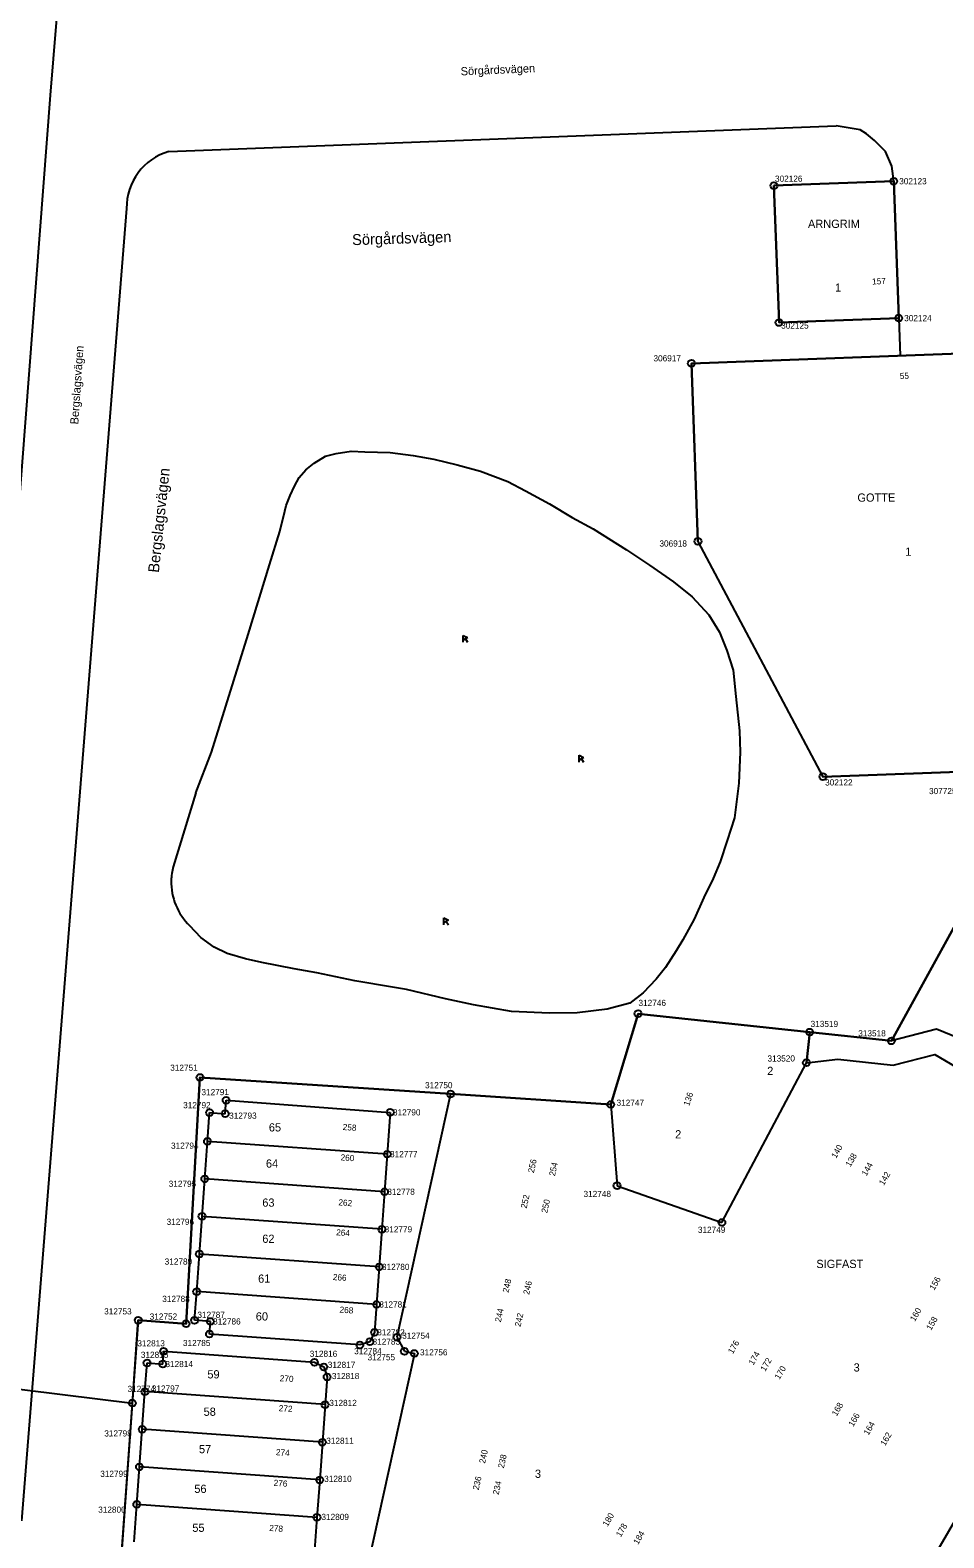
# Model space of a CAD drawing. Extents: x 141995 to 152570, y 6580184 to 6586000.
# Drawn here: x 142442.1 to 142575.6, y 6585148.7 to 6585368.8 of the extents above; entities that cross this region are included whole.
import ezdxf

# ---------------------------------------------------------------- set-up
doc = ezdxf.new("R2010")
doc.units = 0
for name, color, linetype in [('Level 10', 7, 'Continuous'), ('Level 12', 7, 'Continuous'), ('Level 13', 7, 'Continuous'), ('Level 20', 7, 'Continuous'), ('Level 21', 7, 'Continuous'), ('Level 33', 7, 'Continuous'), ('Level 40', 7, 'Continuous'), ('Level 43', 7, 'Continuous'), ('Level 5', 7, 'Continuous'), ('Level 50', 7, 'Continuous'), ('Level 51', 7, 'Continuous'), ('Level 53', 7, 'Continuous'), ('Level 54', 7, 'Continuous'), ('Level 55', 7, 'Continuous'), ('Level 58', 7, 'Continuous'), ('Level 59', 7, 'Continuous'), ('Level 6', 7, 'Continuous'), ('Level 7', 7, 'Continuous'), ('Level 8', 7, 'Continuous')]:
    doc.layers.add(name, color=color, linetype=linetype)

msp = doc.modelspace()

# ---------------------------------------------------------------- linework, layer by layer
at = {"layer": 'Level 10'}
for centre in [(142550.74, 6585346.1), (142568.23, 6585346.74), (142551.48, 6585326.11), (142568.96, 6585326.75), (142538.68, 6585320.14), (142539.64, 6585294.16), (142557.9, 6585259.8), (142530.89, 6585225.21), (142555.96, 6585222.52), (142567.89, 6585221.24), (142555.48, 6585218.05), (142466.9, 6585215.9), (142503.51, 6585213.49), (142470.72, 6585212.57), (142526.9, 6585211.96), (142468.29, 6585210.76), (142470.58, 6585210.6), (142494.69, 6585210.8), (142467.99, 6585206.57), (142494.26, 6585204.7), (142467.6, 6585201.09), (142527.82, 6585200.09), (142493.86, 6585199.21), (142467.2, 6585195.61), (142493.47, 6585193.73), (142543.13, 6585194.73), (142466.81, 6585190.12), (142493.08, 6585188.24), (142466.42, 6585184.63), (142492.69, 6585182.76), (142457.88, 6585180.44), (142466.12, 6585180.44), (142468.42, 6585180.28), (142464.86, 6585179.94), (142468.28, 6585178.44), (142492.39, 6585178.69), (142495.67, 6585177.98), (142461.59, 6585175.92), (142490.25, 6585176.84), (142491.71, 6585177.32), (142496.75, 6585175.92), (142459.16, 6585174.22), (142461.45, 6585174.06), (142483.62, 6585174.31), (142484.98, 6585173.63), (142498.21, 6585175.6), (142485.47, 6585172.18), (142458.86, 6585170.03), (142457.02, 6585168.35), (142485.17, 6585168.14), (142458.46, 6585164.54), (142484.78, 6585162.65), (142458.06, 6585159.05), (142484.38, 6585157.15), (142457.67, 6585153.57), (142483.99, 6585151.67)]:
    msp.add_circle(centre, 0.5, dxfattribs=at)
at = {"layer": 'Level 12'}
for p, q in [((142505.33, 6585279.43), (142505.33, 6585280.43)), ((142505.33, 6585280.43), (142505.98, 6585280.13)), ((142505.98, 6585280.13), (142505.33, 6585279.73)), ((142505.66, 6585279.93), (142505.98, 6585279.43)), ((142522.29, 6585261.93), (142522.29, 6585262.93)), ((142522.29, 6585262.93), (142522.94, 6585262.63)), ((142522.94, 6585262.63), (142522.29, 6585262.23)), ((142522.61, 6585262.43), (142522.94, 6585261.93)), ((142502.54, 6585238.18), (142502.54, 6585239.18)), ((142502.54, 6585239.18), (142503.19, 6585238.88)), ((142503.19, 6585238.88), (142502.54, 6585238.48)), ((142502.87, 6585238.68), (142503.19, 6585238.18))]:
    msp.add_line(p, q, dxfattribs=at)
for points in [[(142479.27, 6585298.57), (142479.48, 6585299.38), (142480.07, 6585300.85), (142480.7, 6585302.24), (142481.4, 6585303.49), (142482.36, 6585304.6), (142483.56, 6585305.57), (142485.22, 6585306.58), (142486.8, 6585307.01), (142488.99, 6585307.32), (142490.98, 6585307.25), (142494.68, 6585307.14), (142498.06, 6585306.69), (142501.04, 6585306.15), (142504.47, 6585305.31), (142507.89, 6585304.39), (142511.88, 6585302.89), (142514.45, 6585301.56), (142517.94, 6585299.65), (142521.27, 6585297.64), (142524.32, 6585295.97), (142529.18, 6585292.93), (142532.55, 6585290.7), (142536.07, 6585288.26), (142538.8, 6585286.08), (142541.23, 6585283.45), (142542.8, 6585280.92), (142543.87, 6585278.22), (142544.78, 6585275.35), (142545.19, 6585271.5), (142545.7, 6585266.48), (142545.79, 6585263.38), (142545.61, 6585258.85), (142544.96, 6585253.81), (142543.92, 6585250.49), (142542.9, 6585247.4), (142541.87, 6585244.94), (142540.51, 6585242.19), (142539.06, 6585238.99), (142537.43, 6585235.99), (142536.44, 6585234.37)], [(142466.31, 6585257.46), (142468.57, 6585263.38), (142473.92, 6585280.57), (142477.03, 6585290.72), (142478.55, 6585295.61), (142479.27, 6585298.57)], [(142466.31, 6585257.46), (142462.97, 6585246.65)], [(142473.57, 6585233.2), (142470.85, 6585233.98), (142468.95, 6585234.93), (142467.04, 6585236.31), (142465.42, 6585238.05)], [(142536.44, 6585234.37), (142534.88, 6585231.94), (142533.51, 6585230.26), (142531.64, 6585228.25), (142529.67, 6585226.72), (142526.37, 6585225.88), (142521.99, 6585225.35), (142517.95, 6585225.26), (142512.4, 6585225.55), (142506.85, 6585226.49), (142502.74, 6585227.36)], [(142502.74, 6585227.36), (142497.04, 6585228.72), (142495, 6585229.08), (142489.54, 6585230.02), (142483.95, 6585231.17), (142480.67, 6585231.75), (142475.94, 6585232.66), (142473.57, 6585233.2)]]:
    msp.add_lwpolyline(points, dxfattribs=at)
for centre, radius, start, end in [((142471.53, 6585244.43), 8.84, 165.4662, 178.5896), ((142471.52, 6585244.43), 8.83, 178.607, 226.2702)]:
    msp.add_arc(centre, radius, start, end, dxfattribs=at)
at = {"layer": 'Level 13'}
for points in [[(142462.35, 6585351.07), (142559.81, 6585354.83)], [(142568.23, 6585346.74), (142567.94, 6585348.96), (142567.05, 6585351.06), (142565.4, 6585352.67), (142564.26, 6585353.68), (142563.31, 6585354.23), (142559.81, 6585354.83)], [(142456.17, 6585342.76), (142440.83, 6585151.19)], [(142568.96, 6585326.75), (142569.16, 6585321.26)]]:
    msp.add_lwpolyline(points, dxfattribs=at)
msp.add_arc((142464.66, 6585342.9), 8.49, 105.7848, 180.9356, dxfattribs=at)
at = {"layer": 'Level 20'}
msp.add_lwpolyline([(142468.56, 6585644.66), (142445.03, 6585359.28), (142436.21, 6585244.62)], dxfattribs=at)
at = {"layer": 'Level 21'}
msp.add_lwpolyline([(142468.56, 6585644.66), (142445.03, 6585359.28), (142436.21, 6585244.62)], dxfattribs=at)
at = {"layer": 'Level 33'}
msp.add_lwpolyline([(142567.89, 6585221.24), (142555.96, 6585222.52), (142555.48, 6585218.05), (142560.06, 6585218.56), (142568.15, 6585217.7), (142574.22, 6585219.27), (142604.74, 6585201.34), (142607.64, 6585198.99), (142608.58, 6585196.76), (142613.29, 6585200.9), (142611.16, 6585202.1), (142607.15, 6585205.72), (142585.42, 6585218.45), (142574.48, 6585222.95)], close=True, dxfattribs=at)
at = {"layer": 'Level 5'}
for points in [[(142550.74, 6585346.1), (142568.23, 6585346.74)], [(142551.48, 6585326.11), (142550.74, 6585346.1)], [(142568.23, 6585346.74), (142568.96, 6585326.75)], [(142568.96, 6585326.75), (142551.48, 6585326.11)], [(142538.68, 6585320.14), (142583.16, 6585321.77)], [(142539.64, 6585294.16), (142538.68, 6585320.14)], [(142539.64, 6585294.16), (142557.9, 6585259.8)], [(142598.87, 6585261.3), (142557.9, 6585259.8)], [(142567.89, 6585221.24), (142578.61, 6585240.72)], [(142526.9, 6585211.96), (142530.89, 6585225.21)], [(142530.89, 6585225.21), (142555.96, 6585222.52)], [(142555.96, 6585222.52), (142567.89, 6585221.24)], [(142464.86, 6585179.94), (142466.9, 6585215.9)], [(142466.9, 6585215.9), (142503.51, 6585213.49)], [(142503.51, 6585213.49), (142526.9, 6585211.96)], [(142457.02, 6585168.35), (142457.88, 6585180.44)], [(142457.88, 6585180.44), (142464.86, 6585179.94)], [(142452.49, 6585105.64), (142457.02, 6585168.35)]]:
    msp.add_lwpolyline(points, dxfattribs=at)
at = {"layer": 'Level 6'}
for points in [[(142550.74, 6585346.1), (142551.48, 6585326.11), (142568.96, 6585326.75), (142568.23, 6585346.74)], [(142539.64, 6585294.16), (142557.9, 6585259.8), (142598.87, 6585261.3), (142596.35, 6585330.26), (142582.86, 6585329.76), (142583.16, 6585321.77), (142538.68, 6585320.14)]]:
    msp.add_lwpolyline(points, close=True, dxfattribs=at)
msp.add_lwpolyline([(142534.91, 6585078.61), (142586.48, 6585167.12), (142592.45, 6585177.46), (142596.9, 6585184.25), (142602.37, 6585190.84), (142608.58, 6585196.76), (142614.41, 6585201.89), (142600.47, 6585217.5), (142599.03, 6585256.98), (142578.05, 6585256.21), (142578.61, 6585240.72), (142567.89, 6585221.24), (142555.96, 6585222.52), (142530.89, 6585225.21), (142526.9, 6585211.96), (142503.51, 6585213.49), (142466.9, 6585215.9), (142464.86, 6585179.94), (142457.88, 6585180.44), (142452.49, 6585105.64)], dxfattribs=at)
at = {"layer": 'Level 7'}
for points in [[(142555.48, 6585218.05), (142555.96, 6585222.52)], [(142543.13, 6585194.73), (142555.48, 6585218.05)], [(142470.58, 6585210.6), (142470.72, 6585212.57)], [(142470.72, 6585212.57), (142494.69, 6585210.8)], [(142503.51, 6585213.49), (142495.67, 6585177.98)], [(142526.9, 6585211.96), (142527.82, 6585200.09)], [(142467.99, 6585206.57), (142468.29, 6585210.76)], [(142468.29, 6585210.76), (142470.58, 6585210.6)], [(142494.69, 6585210.8), (142494.26, 6585204.7)], [(142467.6, 6585201.09), (142467.99, 6585206.57)], [(142494.26, 6585204.7), (142467.99, 6585206.57)], [(142494.26, 6585204.7), (142493.86, 6585199.21)], [(142467.2, 6585195.61), (142467.6, 6585201.09)], [(142493.86, 6585199.21), (142467.6, 6585201.09)], [(142493.86, 6585199.21), (142493.47, 6585193.73)], [(142527.82, 6585200.09), (142543.13, 6585194.73)], [(142466.81, 6585190.12), (142467.2, 6585195.61)], [(142493.47, 6585193.73), (142467.2, 6585195.61)], [(142493.47, 6585193.73), (142493.08, 6585188.24)], [(142466.42, 6585184.63), (142466.81, 6585190.12)], [(142493.08, 6585188.24), (142466.81, 6585190.12)], [(142493.08, 6585188.24), (142492.69, 6585182.76)], [(142466.12, 6585180.44), (142466.42, 6585184.63)], [(142492.69, 6585182.76), (142466.42, 6585184.63)], [(142492.69, 6585182.76), (142492.39, 6585178.69)], [(142468.42, 6585180.28), (142466.12, 6585180.44)], [(142468.28, 6585178.44), (142468.42, 6585180.28)], [(142490.25, 6585176.84), (142468.28, 6585178.44)], [(142492.39, 6585178.69), (142491.71, 6585177.32)], [(142491.71, 6585177.32), (142490.25, 6585176.84)], [(142495.67, 6585177.98), (142496.75, 6585175.92)], [(142458.86, 6585170.03), (142459.16, 6585174.22)], [(142459.16, 6585174.22), (142461.45, 6585174.06)], [(142461.45, 6585174.06), (142461.59, 6585175.92)], [(142461.59, 6585175.92), (142483.62, 6585174.31)], [(142483.62, 6585174.31), (142484.98, 6585173.63)], [(142498.21, 6585175.6), (142491.44, 6585144.94)], [(142496.75, 6585175.92), (142498.21, 6585175.6)], [(142484.98, 6585173.63), (142485.47, 6585172.18)], [(142485.47, 6585172.18), (142485.17, 6585168.14)], [(142458.46, 6585164.54), (142458.86, 6585170.03)], [(142485.17, 6585168.14), (142458.86, 6585170.03)], [(142485.17, 6585168.14), (142484.78, 6585162.65)], [(142458.06, 6585159.05), (142458.46, 6585164.54)], [(142484.78, 6585162.65), (142458.46, 6585164.54)], [(142484.78, 6585162.65), (142484.38, 6585157.15)], [(142457.67, 6585153.57), (142458.06, 6585159.05)], [(142484.38, 6585157.15), (142458.06, 6585159.05)], [(142484.38, 6585157.15), (142483.99, 6585151.67)], [(142457.27, 6585148.08), (142457.67, 6585153.57)], [(142483.99, 6585151.67), (142457.67, 6585153.57)], [(142483.99, 6585151.67), (142483.59, 6585146.19)]]:
    msp.add_lwpolyline(points, dxfattribs=at)
at = {"layer": 'Level 8'}
msp.add_lwpolyline([(142388.97, 6585176.76), (142457.02, 6585168.35)], dxfattribs=at)

# ---------------------------------------------------------------- texts
at = {"layer": 'Level 40'}
for s, rotation, p in [('Sörgårdsvägen', 2.5405, (142505, 6585362.18)), ('Bergslagsvägen', 86.1086, (142449.12, 6585311.21))]:
    msp.add_text(s, height=1.2, rotation=rotation, dxfattribs=at).set_placement(p)
at = {"layer": 'Level 43'}
for s, rotation, p in [('Sörgårdsvägen', 1.8005, (142489.14, 6585337.4)), ('Bergslagsvägen', 83.9525, (142460.89, 6585289.53))]:
    msp.add_text(s, height=1.6, rotation=rotation, dxfattribs=at).set_placement(p)
at = {"layer": 'Level 50'}
for s, rotation, p in [('ARNGRIM', 0.0526, (142555.71, 6585339.92)), ('GOTTE', 0.0522, (142562.93, 6585299.95))]:
    msp.add_text(s, height=1.2, rotation=rotation, dxfattribs=at).set_placement(p)
at = {"layer": 'Level 51'}
for p in [(142559.66, 6585330.61), (142569.92, 6585292.06)]:
    msp.add_text('1', height=1.2, dxfattribs=at).set_placement(p)
for s, p in [('65', (142476.96, 6585208.01)), ('2', (142536.31, 6585207)), ('64', (142476.53, 6585202.73)), ('63', (142476, 6585197.03)), ('62', (142476, 6585191.75)), ('61', (142475.39, 6585185.93)), ('60', (142475.05, 6585180.41)), ('59', (142467.98, 6585171.96)), ('58', (142467.43, 6585166.5)), ('57', (142466.75, 6585161.04)), ('3', (142515.82, 6585157.44)), ('56', (142466.07, 6585155.24)), ('55', (142465.78, 6585149.56))]:
    msp.add_text(s, height=1.2, rotation=0.0522, dxfattribs=at).set_placement(p)
at = {"layer": 'Level 53'}
for s, rotation, p in [('302126', 0.0526, (142550.89, 6585346.66)), ('302123', 0.0526, (142569.03, 6585346.29)), ('302125', 0.0522, (142551.79, 6585325.22)), ('302124', 0.0522, (142569.76, 6585326.3)), ('306917', 0.0526, (142533.14, 6585320.44)), ('306918', 0.0522, (142534.01, 6585293.4)), ('302122', 0.0522, (142558.21, 6585258.52)), ('307725', 0.0522, (142573.39, 6585257.26)), ('312746', 0.0522, (142530.95, 6585226.33)), ('313519', 0.0522, (142556.09, 6585223.26)), ('313518', 0.0522, (142563.05, 6585221.89)), ('313520', 0.0522, (142549.79, 6585218.22)), ('312751', 0.0522, (142462.55, 6585216.87)), ('312791', 0.0522, (142467.11, 6585213.31)), ('312750', 0.0522, (142499.77, 6585214.32)), ('312792', 0.0522, (142464.44, 6585211.4)), ('312747', 0.0522, (142527.75, 6585211.76)), ('312793', 0.0522, (142471.16, 6585209.87)), ('312790', 0.0522, (142495.09, 6585210.35)), ('312794', 0.0522, (142462.67, 6585205.49)), ('312777', 0.0522, (142494.66, 6585204.25)), ('312795', 0.0522, (142462.33, 6585199.93)), ('312778', 0.0522, (142494.26, 6585198.76)), ('312748', 0.0522, (142522.92, 6585198.44)), ('312796', 0.0522, (142462.02, 6585194.38)), ('312779', 0.0522, (142493.87, 6585193.28)), ('312749', 0.0522, (142539.63, 6585193.21)), ('312789', 0.0522, (142461.74, 6585188.57)), ('312780', 0.0522, (142493.48, 6585187.79)), ('312788', 0.0522, (142461.39, 6585183.12)), ('312781', 0.0522, (142493.09, 6585182.31)), ('312753', 0.0522, (142452.9, 6585181.3)), ('312752', 0.0522, (142459.55, 6585180.54)), ('312787', 0.0522, (142466.52, 6585180.8)), ('312786', 0.0522, (142468.82, 6585179.83)), ('312782', 0.0522, (142492.79, 6585178.24)), ('312754', 0.0522, (142496.43, 6585177.75)), ('312813', 0.0522, (142457.75, 6585176.63)), ('312785', 0.0522, (142464.41, 6585176.68)), ('312784', 0.0522, (142489.42, 6585175.49)), ('312783', 0.0522, (142492.11, 6585176.87)), ('312756', 0.0522, (142499.04, 6585175.32)), ('312815', 0.0522, (142458.26, 6585174.96)), ('312814', 0.0522, (142461.85, 6585173.61)), ('312816', 0.0522, (142482.93, 6585175.11)), ('312817', 0.0522, (142485.57, 6585173.5)), ('312755', 0.0522, (142491.38, 6585174.6)), ('312818', 0.0522, (142486.16, 6585171.86)), ('312774', 0.0522, (142456.32, 6585169.98)), ('312797', 0.0522, (142459.86, 6585170.03)), ('312812', 0.0522, (142485.79, 6585167.93)), ('312798', 0.0522, (142452.92, 6585163.48)), ('312811', 0.0522, (142485.34, 6585162.41)), ('312799', 0.0522, (142452.33, 6585157.59)), ('312810', 0.0522, (142485.04, 6585156.85)), ('312800', 0.0522, (142452.03, 6585152.35)), ('312809', 0.0522, (142484.64, 6585151.29))]:
    msp.add_text(s, height=0.9, rotation=rotation, dxfattribs=at).set_placement(p)
at = {"layer": 'Level 54'}
for s, rotation, p in [('157', 2.3442, (142565.09, 6585331.65)), ('136', 71.8572, (142538.35, 6585211.66)), ('258', 355.9711, (142487.72, 6585208.23)), ('140', 59.9447, (142559.81, 6585204.01)), ('138', 59.9447, (142561.9, 6585202.76)), ('260', 355.9711, (142487.41, 6585203.8)), ('256', 77.476, (142515.66, 6585201.9)), ('254', 77.476, (142518.74, 6585201.44)), ('144', 59.9737, (142564.24, 6585201.43)), ('142', 59.9737, (142566.78, 6585200.06)), ('252', 77.476, (142514.61, 6585196.72)), ('262', 355.9331, (142487.09, 6585197.23)), ('250', 77.476, (142517.61, 6585196.04)), ('264', 355.9331, (142486.77, 6585192.86)), ('266', 355.8181, (142486.28, 6585186.33)), ('248', 77.476, (142511.96, 6585184.42)), ('246', 77.476, (142514.97, 6585184.13)), ('156', 59.7646, (142574.14, 6585184.75)), ('268', 355.8181, (142487.26, 6585181.57)), ('244', 77.476, (142510.84, 6585180.11)), ('242', 77.476, (142513.72, 6585179.43)), ('160', 59.7646, (142571.31, 6585180.2)), ('158', 59.7646, (142573.68, 6585178.91)), ('176', 59.7507, (142544.72, 6585175.46)), ('174', 59.7507, (142547.73, 6585173.82)), ('172', 59.7507, (142549.45, 6585172.9)), ('270', 355.9311, (142478.53, 6585171.56)), ('170', 59.7507, (142551.54, 6585171.72)), ('272', 355.9311, (142478.38, 6585167.19)), ('168', 59.9666, (142559.9, 6585166.37)), ('166', 59.9666, (142562.32, 6585164.84)), ('164', 59.9666, (142564.54, 6585163.59)), ('162', 59.7136, (142566.97, 6585162.03)), ('274', 355.9171, (142477.96, 6585160.77)), ('240', 77.61, (142508.53, 6585159.48)), ('238', 77.61, (142511.28, 6585158.79)), ('276', 355.9171, (142477.63, 6585156.28)), ('236', 77.61, (142507.6, 6585155.6)), ('234', 77.61, (142510.52, 6585154.92)), ('180', 59.8287, (142526.43, 6585150.25)), ('278', 355.5341, (142476.99, 6585149.7)), ('178', 59.8287, (142528.36, 6585148.73)), ('184', 59.8427, (142530.89, 6585147.63))]:
    msp.add_text(s, height=0.9, rotation=rotation, dxfattribs=at).set_placement(p)
at = {"layer": 'Level 55'}
msp.add_text('55', height=0.9, rotation=2.0972, dxfattribs=at).set_placement((142569.13, 6585317.85))
at = {"layer": 'Level 58'}
msp.add_text('SIGFAST', height=1.2, rotation=0.0522, dxfattribs=at).set_placement((142556.93, 6585188.08))
at = {"layer": 'Level 59'}
for s, rotation, p in [('2', 0.0522, (142549.75, 6585216.25)), ('3', 0.0514, (142562.37, 6585172.96))]:
    msp.add_text(s, height=1.2, rotation=rotation, dxfattribs=at).set_placement(p)

doc.saveas('drawing.dxf')
